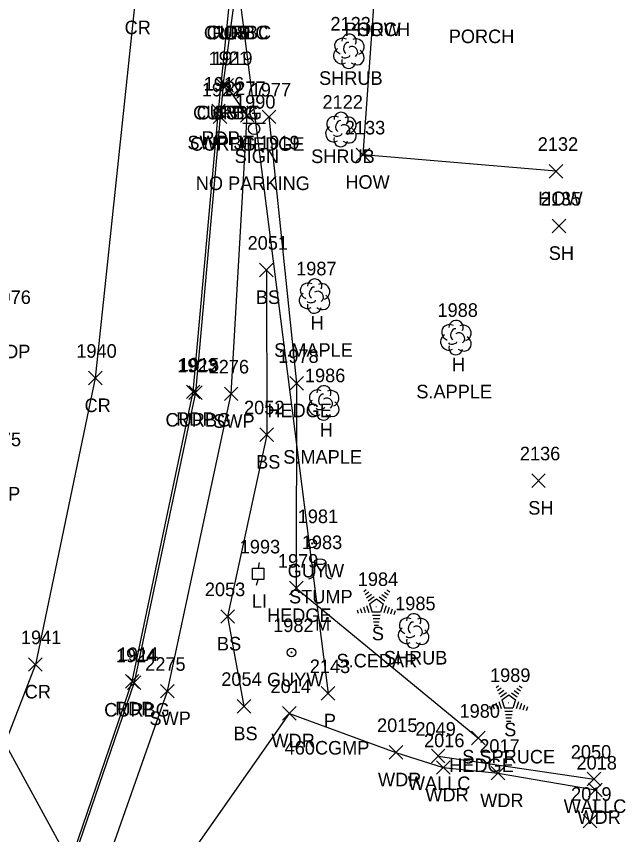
# Model space of a CAD drawing. Extents: x 462930 to 463548, y 29607 to 30453.
# Drawn here: x 463394.45 to 463421.8, y 30209.54 to 30246.27 of the extents above; entities that cross this region are included whole.
import ezdxf

# ---------------------------------------------------------------- set-up
doc = ezdxf.new("R2010")
doc.units = 0
for name, color, linetype in [('D_A', 7, 'Continuous'), ('D_C', 7, 'Continuous'), ('D_I', 7, 'Continuous'), ('D_TIC', 7, 'Continuous'), ('DCP', 7, 'Continuous'), ('L_A', 7, 'Continuous'), ('L_C', 7, 'Continuous'), ('L_I', 7, 'Continuous'), ('L_TIC', 7, 'Continuous'), ('LAHR', 7, 'Continuous'), ('LAWA', 7, 'Continuous'), ('LBC', 7, 'Continuous'), ('LELB', 7, 'Continuous'), ('LSH', 7, 'Continuous'), ('LTC', 7, 'Continuous'), ('LTD', 7, 'Continuous'), ('LTS', 7, 'Continuous'), ('LW', 7, 'Continuous'), ('P_A', 7, 'Continuous'), ('P_I', 7, 'Continuous'), ('P_TIC', 7, 'Continuous'), ('PET', 7, 'Continuous'), ('PRC', 7, 'Continuous'), ('R_A', 7, 'Continuous'), ('R_I', 7, 'Continuous'), ('R_TIC', 7, 'Continuous'), ('RC', 7, 'Continuous'), ('RSW', 7, 'Continuous'), ('S_A', 7, 'Continuous'), ('S_C', 7, 'Continuous'), ('S_I', 7, 'Continuous'), ('SSGN', 7, 'Continuous'), ('U_A', 7, 'Continuous'), ('U_I', 7, 'Continuous'), ('ULP', 7, 'Continuous'), ('UPGW', 7, 'Continuous')]:
    doc.layers.add(name, color=color, linetype=linetype)

msp = doc.modelspace()

# ---------------------------------------------------------------- linework, layer by layer
at = {"layer": 'D_TIC'}
for points in [[(463408.139, 30215.568), (463408.749, 30216.178)], [(463408.749, 30215.568), (463408.139, 30216.178)]]:
    msp.add_lwpolyline(points, dxfattribs=at)
at = {"layer": 'DCP'}
for points in [[(463403.636, 30253.752), (463408.444, 30215.873)], [(463390.996, 30218.997), (463401.362, 30200.025)]]:
    msp.add_lwpolyline(points, dxfattribs=at)
at = {"layer": 'L_TIC'}
for points in [[(463403.426, 30242.859), (463404.036, 30243.469)], [(463404.036, 30242.859), (463403.426, 30243.469)], [(463405.486, 30241.451), (463406.096, 30242.061)], [(463406.096, 30241.451), (463405.486, 30242.061)], [(463409.711, 30239.746), (463410.321, 30240.356)], [(463410.321, 30239.746), (463409.711, 30240.356)], [(463418.371, 30239.009), (463418.981, 30239.619)], [(463418.981, 30239.009), (463418.371, 30239.619)], [(463418.505, 30236.554), (463419.115, 30237.164)], [(463419.115, 30236.554), (463418.505, 30237.164)], [(463405.371, 30234.574), (463405.981, 30235.184)], [(463405.981, 30234.574), (463405.371, 30235.184)], [(463406.723, 30229.491), (463407.333, 30230.101)], [(463407.333, 30229.491), (463406.723, 30230.101)], [(463405.384, 30227.184), (463405.994, 30227.794)], [(463405.994, 30227.184), (463405.384, 30227.794)], [(463417.585, 30225.119), (463418.195, 30225.729)], [(463418.195, 30225.119), (463417.585, 30225.729)], [(463406.709, 30220.3), (463407.319, 30220.91)], [(463407.319, 30220.3), (463406.709, 30220.91)], [(463403.626, 30219.021), (463404.236, 30219.631)], [(463404.236, 30219.021), (463403.626, 30219.631)], [(463404.364, 30214.992), (463404.974, 30215.602)], [(463404.974, 30214.992), (463404.364, 30215.602)], [(463406.401, 30214.674), (463407.011, 30215.284)], [(463407.011, 30214.674), (463406.401, 30215.284)], [(463414.886, 30213.564), (463415.496, 30214.174)], [(463415.496, 30213.564), (463414.886, 30214.174)], [(463411.182, 30212.923), (463411.792, 30213.533)], [(463411.792, 30212.923), (463411.182, 30213.533)], [(463413.079, 30212.755), (463413.689, 30213.365)], [(463413.689, 30212.755), (463413.079, 30213.365)], [(463413.309, 30212.243), (463413.919, 30212.853)], [(463413.919, 30212.243), (463413.309, 30212.853)], [(463415.77, 30211.99), (463416.38, 30212.6)], [(463416.38, 30211.99), (463415.77, 30212.6)], [(463420.078, 30211.728), (463420.688, 30212.338)], [(463420.688, 30211.728), (463420.078, 30212.338)], [(463420.135, 30211.237), (463420.745, 30211.847)], [(463420.745, 30211.237), (463420.135, 30211.847)], [(463419.894, 30209.836), (463420.504, 30210.446)], [(463420.504, 30209.836), (463419.894, 30210.446)]]:
    msp.add_lwpolyline(points, dxfattribs=at)
at = {"layer": 'LAHR'}
msp.add_lwpolyline([(463405.791, 30241.756), (463407.028, 30229.796), (463407.014, 30220.605), (463415.191, 30213.869)], dxfattribs=at)
at = {"layer": 'LAWA'}
msp.add_lwpolyline([(463387.88, 30168.775), (463397.819, 30177.75), (463407.759, 30184.507), (463409.113, 30187.695), (463404.765, 30189.586), (463395.481, 30185.625), (463385.697, 30177.467), (463383.154, 30179.845), (463389.311, 30188.588), (463395.273, 30197.676), (463398.338, 30200.205), (463401.253, 30207.173), (463406.706, 30214.979), (463411.487, 30213.228), (463413.614, 30212.548), (463416.075, 30212.295), (463420.44, 30211.542)], dxfattribs=at)
at = {"layer": 'LBC'}
msp.add_lwpolyline([(463418.676, 30239.314), (463410.016, 30240.051), (463410.515, 30246.903)], dxfattribs=at)
at = {"layer": 'LELB'}
for points in [[(463403.731, 30243.164), (463404.214, 30246.758)], [(463405.676, 30234.879), (463405.689, 30227.489), (463403.931, 30219.326), (463404.669, 30215.297)]]:
    msp.add_lwpolyline(points, dxfattribs=at)
at = {"layer": 'LSH'}
for p, q in [((463409.371, 30244.714), (463409.371, 30244.714)), ((463409.371, 30244.714), (463409.371, 30244.714)), ((463409.015, 30241.204), (463409.015, 30241.204)), ((463409.015, 30241.204), (463409.015, 30241.204)), ((463412.276, 30218.696), (463412.276, 30218.696)), ((463412.276, 30218.696), (463412.276, 30218.696))]:
    msp.add_line(p, q, dxfattribs=at)
for centre in [(463409.385, 30245.151), (463409.029, 30241.641), (463412.29, 30219.133)]:
    msp.add_arc(centre, 0.319, 335.5272, 180.9563, dxfattribs=at)
for centre, major_axis, ratio, start_param, end_param in [((463409.13, 30244.917), (0.369, -0.156), 0.895232, 1.570796, 4.712389), ((463409.307, 30244.854), (-0.063, -0.241), 0.645439, 3.141593, 6.283185), ((463409.688, 30244.892), (-0.348, -0.147), 0.949671, 1.570796, 4.712389), ((463409.041, 30244.498), (0.178, -0.317), 0.959034, 3.141593, 6.283185), ((463409.523, 30244.663), (-0.152, 0.203), 0.989748, 3.141593, 6.283185), ((463409.676, 30244.46), (-0.332, 0.241), 0.841452, 1.570796, 4.712389), ((463409.371, 30244.257), (0.081, 0.323), 0.942809, 1.570796, 4.712389), ((463409.231, 30244.485), (-0.19, -0.025), 0.423636, 0, 3.141593), ((463408.774, 30241.407), (0.369, -0.156), 0.895232, 1.570796, 4.712389), ((463409.332, 30241.382), (-0.348, -0.147), 0.949671, 1.570796, 4.712389), ((463408.951, 30241.344), (-0.063, -0.241), 0.645439, 3.141593, 6.283185), ((463409.167, 30241.153), (-0.152, 0.203), 0.989748, 3.141593, 6.283185), ((463408.685, 30240.988), (0.178, -0.317), 0.959034, 3.141593, 6.283185), ((463408.875, 30240.975), (-0.19, -0.025), 0.423636, 0, 3.141593), ((463409.32, 30240.95), (-0.332, 0.241), 0.841452, 1.570796, 4.712389), ((463409.015, 30240.747), (0.081, 0.323), 0.942809, 1.570796, 4.712389), ((463412.035, 30218.899), (0.369, -0.156), 0.895232, 1.570796, 4.712389), ((463412.212, 30218.836), (-0.063, -0.241), 0.645439, 3.141593, 6.283185), ((463412.593, 30218.874), (-0.348, -0.147), 0.949671, 1.570796, 4.712389), ((463411.946, 30218.48), (0.178, -0.317), 0.959034, 3.141593, 6.283185), ((463412.428, 30218.645), (-0.152, 0.203), 0.989748, 3.141593, 6.283185), ((463412.581, 30218.442), (-0.332, 0.241), 0.841452, 1.570796, 4.712389), ((463412.276, 30218.239), (0.081, 0.323), 0.942809, 1.570796, 4.712389), ((463412.136, 30218.467), (-0.19, -0.025), 0.423636, 0, 3.141593)]:
    msp.add_ellipse(centre, major_axis=major_axis, ratio=ratio, start_param=start_param, end_param=end_param, dxfattribs=at)
at = {"layer": 'LTC'}
for p, q in [((463410.047, 30220.456), (463410.155, 30220.535)), ((463410.111, 30220.314), (463410.272, 30220.431)), ((463410.97, 30220.423), (463411.137, 30220.301)), ((463411.083, 30220.529), (463411.21, 30220.436)), ((463410.175, 30220.172), (463410.389, 30220.328)), ((463410.239, 30220.03), (463410.506, 30220.225)), ((463410.307, 30219.892), (463410.615, 30220.115)), ((463410.615, 30220.115), (463410.919, 30219.894)), ((463410.743, 30220.211), (463410.99, 30220.031)), ((463410.857, 30220.317), (463411.064, 30220.166)), ((463409.891, 30219.693), (463409.955, 30219.494)), ((463410.03, 30219.759), (463410.112, 30219.504)), ((463410.168, 30219.825), (463410.269, 30219.514)), ((463410.307, 30219.892), (463410.425, 30219.528)), ((463410.919, 30219.894), (463410.8, 30219.528)), ((463411.053, 30219.812), (463410.95, 30219.495)), ((463411.188, 30219.736), (463411.1, 30219.466)), ((463409.752, 30219.627), (463409.798, 30219.484)), ((463410.8, 30219.528), (463410.425, 30219.528)), ((463410.788, 30219.375), (463410.439, 30219.375)), ((463411.324, 30219.659), (463411.251, 30219.437)), ((463411.459, 30219.583), (463411.402, 30219.408)), ((463410.763, 30219.223), (463410.462, 30219.223)), ((463410.737, 30219.071), (463410.484, 30219.071)), ((463410.712, 30218.918), (463410.506, 30218.918)), ((463415.986, 30216.147), (463416.094, 30216.226)), ((463416.05, 30216.005), (463416.211, 30216.122)), ((463416.114, 30215.863), (463416.328, 30216.019)), ((463416.909, 30216.114), (463417.076, 30215.992)), ((463417.022, 30216.22), (463417.149, 30216.127)), ((463416.178, 30215.721), (463416.445, 30215.916)), ((463416.246, 30215.583), (463416.554, 30215.806)), ((463416.554, 30215.806), (463416.858, 30215.585)), ((463416.682, 30215.902), (463416.929, 30215.722)), ((463416.796, 30216.008), (463417.003, 30215.857)), ((463415.691, 30215.318), (463415.737, 30215.175)), ((463415.83, 30215.384), (463415.894, 30215.185)), ((463415.969, 30215.45), (463416.051, 30215.195)), ((463416.107, 30215.516), (463416.208, 30215.205)), ((463416.246, 30215.583), (463416.364, 30215.219)), ((463416.858, 30215.585), (463416.739, 30215.219)), ((463416.992, 30215.503), (463416.889, 30215.186)), ((463417.127, 30215.427), (463417.039, 30215.157)), ((463417.263, 30215.35), (463417.19, 30215.128)), ((463416.739, 30215.219), (463416.364, 30215.219)), ((463416.727, 30215.066), (463416.378, 30215.066)), ((463416.702, 30214.914), (463416.401, 30214.914)), ((463417.398, 30215.274), (463417.341, 30215.099)), ((463416.676, 30214.762), (463416.423, 30214.762)), ((463416.651, 30214.609), (463416.445, 30214.609))]:
    msp.add_line(p, q, dxfattribs=at)
at = {"layer": 'LTD'}
for p, q in [((463407.831, 30233.726), (463407.831, 30233.726)), ((463407.831, 30233.726), (463407.831, 30233.726)), ((463414.176, 30231.862), (463414.176, 30231.862)), ((463414.176, 30231.862), (463414.176, 30231.862)), ((463408.242, 30228.929), (463408.242, 30228.929)), ((463408.242, 30228.929), (463408.242, 30228.929))]:
    msp.add_line(p, q, dxfattribs=at)
for centre in [(463407.845, 30234.163), (463414.19, 30232.299), (463408.256, 30229.366)]:
    msp.add_arc(centre, 0.319, 335.5272, 180.9563, dxfattribs=at)
for centre, major_axis, ratio, start_param, end_param in [((463407.59, 30233.929), (0.369, -0.156), 0.895232, 1.570796, 4.712389), ((463407.767, 30233.866), (-0.063, -0.241), 0.645439, 3.141593, 6.283185), ((463408.148, 30233.904), (-0.348, -0.147), 0.949671, 1.570796, 4.712389), ((463407.501, 30233.51), (0.178, -0.317), 0.959034, 3.141593, 6.283185), ((463407.983, 30233.675), (-0.152, 0.203), 0.989748, 3.141593, 6.283185), ((463408.136, 30233.472), (-0.332, 0.241), 0.841452, 1.570796, 4.712389), ((463407.831, 30233.269), (0.081, 0.323), 0.942809, 1.570796, 4.712389), ((463407.691, 30233.497), (-0.19, -0.025), 0.423636, 0, 3.141593), ((463413.935, 30232.065), (0.369, -0.156), 0.895232, 1.570796, 4.712389), ((463414.112, 30232.002), (-0.063, -0.241), 0.645439, 3.141593, 6.283185), ((463414.493, 30232.04), (-0.348, -0.147), 0.949671, 1.570796, 4.712389), ((463413.846, 30231.646), (0.178, -0.317), 0.959034, 3.141593, 6.283185), ((463414.328, 30231.811), (-0.152, 0.203), 0.989748, 3.141593, 6.283185), ((463414.481, 30231.608), (-0.332, 0.241), 0.841452, 1.570796, 4.712389), ((463414.176, 30231.405), (0.081, 0.323), 0.942809, 1.570796, 4.712389), ((463414.036, 30231.633), (-0.19, -0.025), 0.423636, 0, 3.141593), ((463408.001, 30229.132), (0.369, -0.156), 0.895232, 1.570796, 4.712389), ((463408.178, 30229.069), (-0.063, -0.241), 0.645439, 3.141593, 6.283185), ((463408.559, 30229.107), (-0.348, -0.147), 0.949671, 1.570796, 4.712389), ((463407.912, 30228.713), (0.178, -0.317), 0.959034, 3.141593, 6.283185), ((463408.394, 30228.878), (-0.152, 0.203), 0.989748, 3.141593, 6.283185), ((463408.547, 30228.675), (-0.332, 0.241), 0.841452, 1.570796, 4.712389), ((463408.242, 30228.472), (0.081, 0.323), 0.942809, 1.570796, 4.712389), ((463408.102, 30228.7), (-0.19, -0.025), 0.423636, 0, 3.141593)]:
    msp.add_ellipse(centre, major_axis=major_axis, ratio=ratio, start_param=start_param, end_param=end_param, dxfattribs=at)
at = {"layer": 'LTS'}
for p, q in [((463407.832, 30221.785), (463407.832, 30221.277)), ((463408.34, 30221.735), (463408.34, 30221.785)), ((463408.34, 30221.785), (463408.34, 30221.277)), ((463408.086, 30221.437), (463408.086, 30221.437)), ((463408.086, 30221.437), (463408.086, 30221.437)), ((463408.086, 30221.43), (463408.086, 30221.43))]:
    msp.add_line(p, q, dxfattribs=at)
msp.add_circle((463408.086, 30221.437), 0.0254, dxfattribs=at)
for centre, start, end in [((463407.578, 30221.277), 270, 360), ((463408.594, 30221.277), 180, 270)]:
    msp.add_arc(centre, 0.254, start, end, dxfattribs=at)
msp.add_ellipse((463408.086, 30221.785), major_axis=(-0.254, 0), ratio=0.5, dxfattribs=at)
at = {"layer": 'LW'}
msp.add_lwpolyline([(463413.384, 30213.06), (463420.383, 30212.033)], dxfattribs=at)
at = {"layer": 'P_TIC'}
for points in [[(463403.22, 30241.715), (463403.83, 30242.325)], [(463403.83, 30241.715), (463403.22, 30242.325)], [(463397.686, 30229.722), (463398.296, 30230.332)], [(463398.296, 30229.722), (463397.686, 30230.332)], [(463402.084, 30229.106), (463402.694, 30229.716)], [(463402.694, 30229.106), (463402.084, 30229.716)], [(463394.999, 30216.867), (463395.609, 30217.477)], [(463395.609, 30216.867), (463394.999, 30217.477)], [(463399.345, 30216.108), (463399.955, 30216.718)], [(463399.955, 30216.108), (463399.345, 30216.718)]]:
    msp.add_lwpolyline(points, dxfattribs=at)
at = {"layer": 'PET'}
msp.add_lwpolyline([(463357.128, 30146.779), (463364.23, 30160.089), (463372.211, 30170.687), (463380.439, 30181.089), (463388.986, 30192.495), (463395.438, 30204.072), (463399.65, 30216.413), (463402.389, 30229.411), (463403.525, 30242.02), (463404.007, 30246.74), (463403.926, 30248.538), (463404.123, 30251.434)], dxfattribs=at)
at = {"layer": 'PRC'}
msp.add_lwpolyline([(463399.789, 30246.987), (463397.991, 30230.027), (463395.304, 30217.172), (463391.095, 30206.312), (463384.492, 30195.113), (463376.573, 30184.227), (463367.848, 30173.371), (463360.659, 30162.372), (463353.283, 30149.309)], dxfattribs=at)
at = {"layer": 'R_TIC'}
for points in [[(463403.426, 30242.859), (463404.036, 30243.469)], [(463404.036, 30242.859), (463403.426, 30243.469)], [(463403.583, 30242.859), (463404.193, 30243.469)], [(463404.193, 30242.859), (463403.583, 30243.469)], [(463404.512, 30241.514), (463405.122, 30242.124)], [(463405.122, 30241.514), (463404.512, 30242.124)], [(463403.293, 30241.454), (463403.903, 30242.064)], [(463403.903, 30241.454), (463403.293, 30242.064)], [(463402.187, 30229.07), (463402.797, 30229.68)], [(463402.797, 30229.07), (463402.187, 30229.68)], [(463403.788, 30229.016), (463404.398, 30229.626)], [(463404.398, 30229.016), (463403.788, 30229.626)], [(463399.435, 30216.054), (463400.045, 30216.664)], [(463400.045, 30216.054), (463399.435, 30216.664)], [(463400.924, 30215.672), (463401.534, 30216.282)], [(463401.534, 30215.672), (463400.924, 30216.282)]]:
    msp.add_lwpolyline(points, dxfattribs=at)
at = {"layer": 'RC'}
msp.add_lwpolyline([(463403.888, 30243.164), (463403.731, 30243.164), (463403.598, 30241.759), (463402.492, 30229.375), (463399.74, 30216.359), (463395.506, 30204.018), (463389.016, 30192.435), (463380.487, 30181.016), (463372.297, 30170.609), (463364.316, 30160.034), (463357.246, 30146.767)], dxfattribs=at)
at = {"layer": 'RSW'}
for points in [[(463404.817, 30241.819), (463403.888, 30243.164)], [(463365.586, 30159.156), (463373.394, 30169.643), (463381.656, 30180.281), (463390.273, 30191.668), (463396.887, 30203.599), (463401.229, 30215.977), (463404.093, 30229.321), (463404.817, 30241.819)]]:
    msp.add_lwpolyline(points, dxfattribs=at)
at = {"layer": 'SSGN'}
for p, q in [((463404.619, 30241.471), (463405.635, 30241.471)), ((463405.121, 30241.217), (463405.121, 30241.217))]:
    msp.add_line(p, q, dxfattribs=at)
msp.add_circle((463405.121, 30241.217), 0.254, dxfattribs=at)
at = {"layer": 'ULP'}
for p, q in [((463405.351, 30221.752), (463405.3, 30221.498)), ((463405.046, 30220.99), (463405.046, 30221.498)), ((463405.046, 30221.498), (463405.554, 30221.498)), ((463405.3, 30221.244), (463405.3, 30221.244)), ((463405.554, 30221.498), (463405.554, 30220.99)), ((463405.554, 30220.99), (463405.046, 30220.99)), ((463405.224, 30220.736), (463405.3, 30220.99))]:
    msp.add_line(p, q, dxfattribs=at)
at = {"layer": 'UPGW'}
for centre, radius in [((463407.729, 30222.605), 0.191), ((463407.729, 30222.605), 0.0254), ((463406.8, 30217.715), 0.191), ((463406.8, 30217.715), 0.0254)]:
    msp.add_circle(centre, radius, dxfattribs=at)

# ---------------------------------------------------------------- texts
at = {"layer": 'D_A'}
msp.add_text('P', height=0.61, dxfattribs=at).set_placement((463408.254, 30214.349))
at = {"layer": 'D_C'}
msp.add_text('460CGMP', height=0.6096, dxfattribs=at).set_placement((463406.493, 30213.13))
at = {"layer": 'D_I'}
msp.add_text('2143', height=0.6096, dxfattribs=at).set_placement((463407.623, 30216.787))
at = {"layer": 'L_A'}
for s, height, p in [('CS', 0.6096, (463403.739, 30245.234)), ('PORCH', 0.6096, (463409.181, 30245.379)), ('HOW', 0.6096, (463409.718, 30245.379)), ('PORCH', 0.6096, (463413.86, 30245.064)), ('SHRUB', 0.6096, (463408.039, 30243.19)), ('CS', 0.6096, (463403.256, 30241.64)), ('HEDGE', 0.6096, (463404.481, 30240.232)), ('SHRUB', 0.6096, (463407.683, 30239.68)), ('HOW', 0.6096, (463409.219, 30238.527)), ('HOW', 0.6096, (463417.879, 30237.79)), ('SH', 0.6096, (463418.349, 30235.335)), ('BS', 0.6096, (463405.201, 30233.355)), ('H', 0.61, (463407.658, 30232.202)), ('H', 0.61, (463414.003, 30230.338)), ('HEDGE', 0.6096, (463405.718, 30228.272)), ('H', 0.61, (463408.069, 30227.405)), ('BS', 0.6096, (463405.214, 30225.965)), ('SH', 0.6096, (463417.429, 30223.9)), ('STUMP', 0.6096, (463406.691, 30219.914)), ('HEDGE', 0.6096, (463405.704, 30219.081)), ('S', 0.61, (463410.41, 30218.259)), ('BS', 0.6096, (463403.456, 30217.802)), ('SHRUB', 0.6096, (463410.944, 30217.172)), ('S', 0.61, (463416.349, 30213.95)), ('BS', 0.6096, (463404.194, 30213.773)), ('WDR', 0.6096, (463405.902, 30213.455)), ('HEDGE', 0.6096, (463413.881, 30212.345)), ('WDR', 0.6096, (463410.683, 30211.704)), ('WALLC', 0.6096, (463412.023, 30211.536)), ('WDR', 0.6096, (463412.81, 30211.024)), ('WDR', 0.6096, (463415.271, 30210.771)), ('WALLC', 0.6096, (463419.022, 30210.509)), ('WDR', 0.6096, (463419.636, 30210.018))]:
    msp.add_text(s, height=height, dxfattribs=at).set_placement(p)
at = {"layer": 'L_C'}
for s, height, p in [('S.MAPLE', 0.6096, (463406.021, 30230.983)), ('S.APPLE', 0.6096, (463412.405, 30229.119)), ('S.MAPLE', 0.6096, (463406.432, 30226.186)), ('M', 0.61, (463407.859, 30218.695)), ('S.CEDAR', 0.6096, (463408.823, 30217.04)), ('S.SPRUCE', 0.6096, (463414.467, 30212.731))]:
    msp.add_text(s, height=height, dxfattribs=at).set_placement(p)
at = {"layer": 'L_I'}
for s, p in [('2123', (463408.55, 30245.628)), ('1921', (463403.083, 30244.078)), ('1977', (463404.97, 30242.67)), ('2122', (463408.194, 30242.118)), ('2133', (463409.195, 30240.965)), ('2132', (463417.855, 30240.228)), ('2135', (463417.989, 30237.773)), ('2051', (463404.831, 30235.793)), ('1987', (463407.01, 30234.64)), ('1988', (463413.355, 30232.776)), ('1978', (463406.207, 30230.71)), ('1986', (463407.404, 30229.843)), ('2052', (463404.671, 30228.403)), ('2136', (463417.052, 30226.338)), ('1983', (463407.264, 30222.352)), ('1979', (463406.191, 30221.519)), ('1984', (463409.776, 30220.697)), ('2053', (463402.913, 30220.24)), ('1985', (463411.455, 30219.61)), ('2054', (463403.651, 30216.211)), ('1989', (463415.713, 30216.388)), ('2014', (463405.861, 30215.893)), ('1980', (463414.344, 30214.783)), ('2015', (463410.642, 30214.142)), ('2049', (463412.364, 30213.974)), ('2016', (463412.752, 30213.462)), ('2017', (463415.23, 30213.209)), ('2050', (463419.339, 30212.947)), ('2018', (463419.595, 30212.456)), ('2019', (463419.352, 30211.055))]:
    msp.add_text(s, height=0.6096, dxfattribs=at).set_placement(p)
at = {"layer": 'LTC'}
for p in [(463410.58, 30219.815), (463416.519, 30215.506)]:
    msp.add_text('.', height=0.316, rotation=270, dxfattribs=at).set_placement(p)
at = {"layer": 'P_A'}
for s, p in [('CR', (463399.311, 30245.463)), ('RDP', (463403.241, 30245.216)), ('RDP', (463402.759, 30240.496)), ('RDP', (463393.361, 30230.918)), ('CR', (463397.513, 30228.503)), ('RDP', (463401.623, 30227.887)), ('RDP', (463392.905, 30224.532)), ('CR', (463394.826, 30215.648)), ('RDP', (463398.884, 30214.889))]:
    msp.add_text(s, height=0.6096, dxfattribs=at).set_placement(p)
at = {"layer": 'P_I'}
for s, p in [('1916', (463402.86, 30242.934)), ('1976', (463393.289, 30233.356)), ('1940', (463397.144, 30230.941)), ('1915', (463401.741, 30230.325)), ('1975', (463392.85, 30226.97)), ('1941', (463394.656, 30218.086)), ('1914', (463399.002, 30217.327))]:
    msp.add_text(s, height=0.6096, dxfattribs=at).set_placement(p)
at = {"layer": 'R_A'}
for s, p in [('CURBC', (463402.868, 30245.234)), ('CURBC', (463402.99, 30245.238)), ('CURBG', (463402.385, 30241.64)), ('CURBG', (463402.542, 30241.64)), ('SWP JT 1919', (463402.132, 30240.295)), ('CURBG', (463402.252, 30240.235)), ('CURBG', (463401.146, 30227.851)), ('SWP', (463403.289, 30227.797)), ('CURBG', (463398.394, 30214.835)), ('SWP', (463400.425, 30214.453))]:
    msp.add_text(s, height=0.6096, dxfattribs=at).set_placement(p)
at = {"layer": 'R_I'}
for s, p in [('1921', (463403.083, 30244.078)), ('1919', (463403.238, 30244.078)), ('1922', (463402.777, 30242.673)), ('2277', (463403.823, 30242.733)), ('1923', (463401.671, 30230.289)), ('2276', (463403.083, 30230.235)), ('1924', (463398.919, 30217.273)), ('2275', (463400.235, 30216.891))]:
    msp.add_text(s, height=0.6096, dxfattribs=at).set_placement(p)
at = {"layer": 'S_A'}
msp.add_text('SIGN', height=0.6096, dxfattribs=at).set_placement((463404.249, 30239.687))
at = {"layer": 'S_C'}
msp.add_text('NO PARKING', height=0.6096, dxfattribs=at).set_placement((463402.506, 30238.468))
at = {"layer": 'S_I'}
msp.add_text('1990', height=0.6096, dxfattribs=at).set_placement((463404.268, 30242.125))
at = {"layer": 'U_A'}
for s, p in [('GUYW', (463406.63, 30221.081)), ('LI', (463405.026, 30219.72)), ('GUYW', (463405.701, 30216.191))]:
    msp.add_text(s, height=0.6096, dxfattribs=at).set_placement(p)
at = {"layer": 'U_I'}
for s, p in [('1981', (463407.081, 30223.519)), ('1993', (463404.479, 30222.158)), ('1982', (463405.979, 30218.629))]:
    msp.add_text(s, height=0.6096, dxfattribs=at).set_placement(p)

doc.saveas('drawing.dxf')
